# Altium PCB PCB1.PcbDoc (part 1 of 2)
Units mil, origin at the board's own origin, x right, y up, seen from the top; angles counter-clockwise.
Board outline 3035 x 2265 mil, 2 copper layers (Top Layer, Bottom Layer); 66 components, 70 nets, 274 pads, 24 vias.
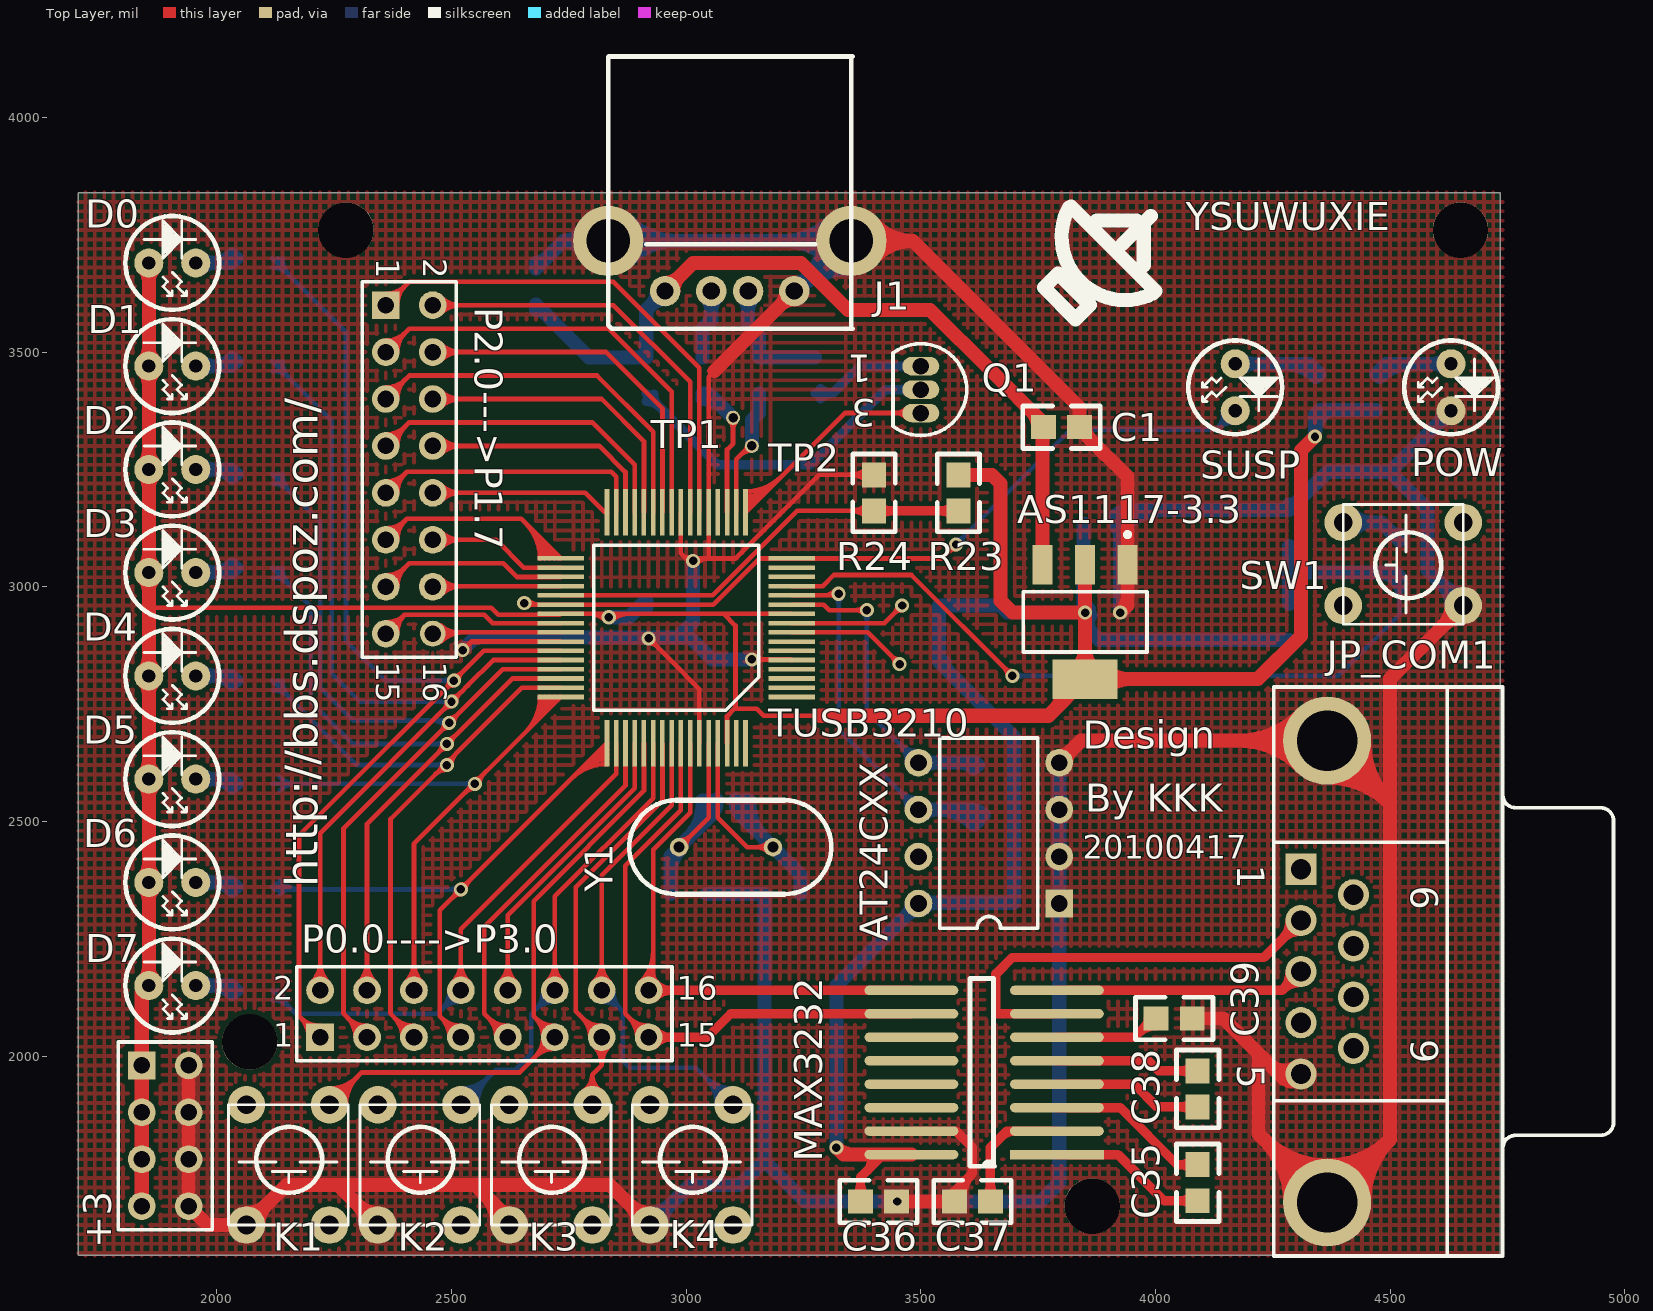
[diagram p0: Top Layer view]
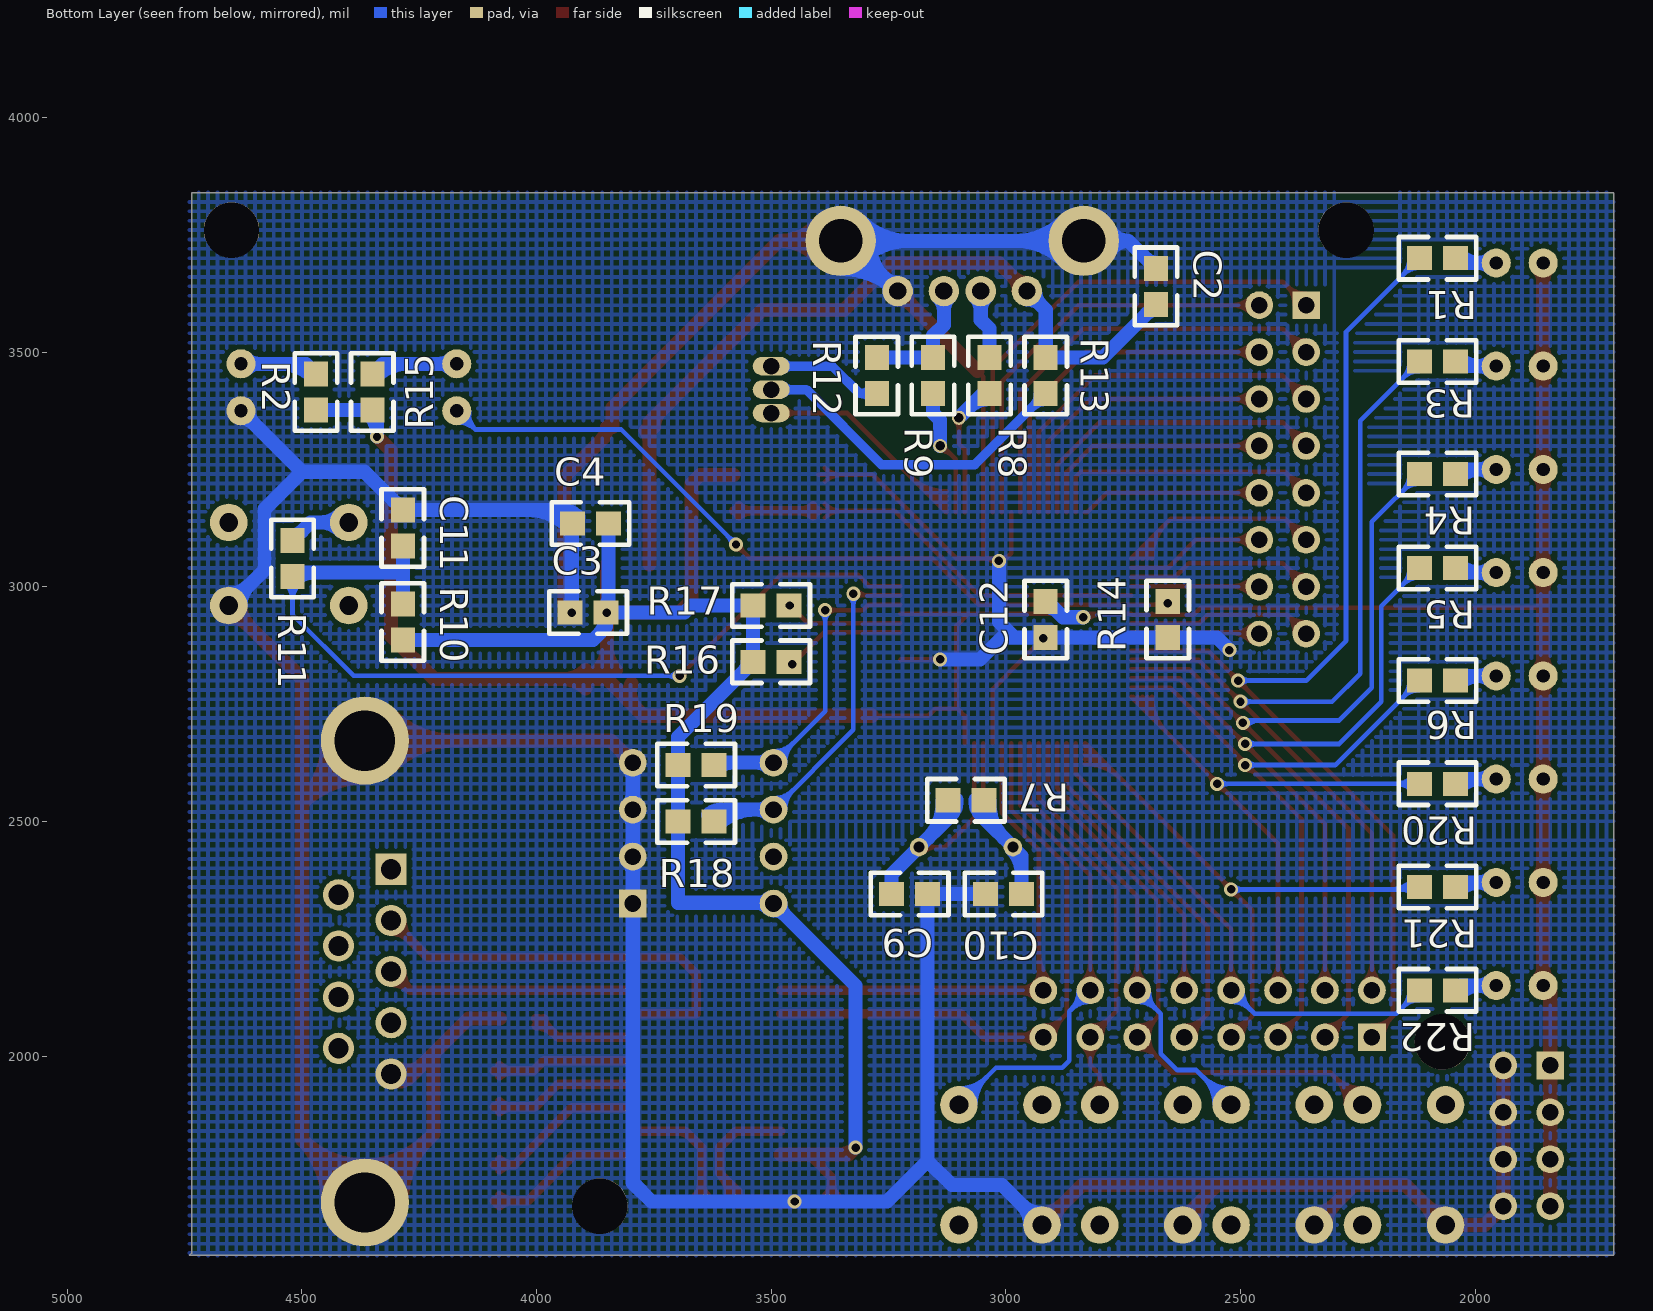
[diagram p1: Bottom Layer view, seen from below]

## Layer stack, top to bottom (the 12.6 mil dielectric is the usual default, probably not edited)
Top Layer: signal copper 1.4
Dielectric: dielectric 12.6, FR-4, Dk 4.8
Bottom Layer: signal copper 1.4

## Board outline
1705,3840 1705,1575 4740,1575 4735,1580 4735,3840

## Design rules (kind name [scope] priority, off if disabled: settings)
Clearance [All] p1: gap=5
HoleSize [All] p1: absolutevalues=TRUE maxlimit=300 minlimit=1 maxpercent=80.000 minpercent=20.000
PolygonConnect [All] p1: connectstyle=Direct reliefconductorwidth=10 reliefentries=4 polygonreliefangle="90 Angle"
RoutingVias [All] p1: holewidth=18 width=30 viastyle="Through Hole" minholewidth=18 minwidth=30 maxholewidth=18 maxwidth=30
SilkscreenOverComponentPads [All] p1: minsilkscreentomaskgap=10
SolderMaskExpansion [All] p1: expansion=4
TestPointUsage [All] p1: valid=0 allowmultiple=FALSE
Testpoint [All] p1: side=15 testpointundercomponent=TRUE minsize=40 maxsize=100 preferedsize=60 minholesize=0 maxholesize=40 preferedholesize=32 testpointgrid=1 style=1023 order=0123456789
Width [All] p1: maxlimit=50 minlimit=5 preferedwidth=50
22 further rules are at their usual default settings.

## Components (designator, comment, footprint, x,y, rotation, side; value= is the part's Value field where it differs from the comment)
+3 "Header 4X2" HDR2X4 1840,1980 r270 top (schematic designator "+3.3  GND")
AS1117-3.3 "AS1117-3.3" DSO-G3 3850,2925 r180 top
AT24CXX "24LCxx" DIP-8 3645,2475 r90 top (schematic designator U5)
C1 "Cap" C0805 3800,3340 r180 top
C2 "Cap" C0805 2680,3640 r270 bottom
C3 "Cap" C0805 3890,2945 r180 bottom
C4 "Cap" C0805 3885,3135 r180 bottom
C9 "Cap" C0805 3205,2345 r180 bottom
C10 "Cap" C0805 3005,2345 r0 bottom
C11 "Cap" C0805 4285,3125 r90 bottom
C12 "Cap" C0805 2915,2930 r90 bottom
C35 "Cap" C0805 4090,1730 r90 top
C36 "Cap" C0805 3410,1690 r0 top
C37 "Cap" C0805 3610,1690 r0 top
C38 "Cap" C0805 4090,1930 r90 top
C39 "Cap" C0805 4040,2080 r180 top
D0 "LED1" LED 1855,3690 r0 top
D1 "LED1" LED 1855,3470 r0 top
D2 "LED1" LED 1855,3250 r0 top
D3 "LED1" LED 1855,3030 r0 top
D4 "LED1" LED 1855,2810 r0 top
D5 "LED1" LED 1855,2590 r0 top
D6 "LED1" LED 1855,2370 r0 top
D7 "LED1" LED 1855,2150 r0 top
J1 "USB_A" USB-A 2955,3630 r180 top
JP_COM1 "D Connector 9" DSUB1.385-2H9 4740,2180 r270 top
K1 "Button" SW-6 2240,1640 r90 top
K2 "Button" SW-6 2520,1640 r90 top
K3 "Button" SW-6 2800,1640 r90 top
K4 "Button" SW-6 3100,1640 r90 top
MAX3232 "MAX3232" SOP16 3770,1790 r180 top (schematic designator U6)
P0.0---->P3.0 "Header 8X2" HDR2X8#1 2220,2040 r0 top (schematic designator P1)
P2.0--->P1.7 "Header 8X2" HDR2X8#2 2360,3600 r270 top (schematic designator P2)
POW "LED1" LED 4630,3475 r270 top
Q1 "2N3904" TO-92A 3500,3420 r180 top
R1 "Res2" c0805 2080,3700 r180 bottom
R2 "Res2" c0805 4470,3415 r90 bottom
R3 "Res2" c0805 2080,3480 r180 bottom
R4 "Res2" c0805 2080,3240 r180 bottom
R5 "Res2" c0805 2080,3040 r180 bottom
R6 "Res2" c0805 2080,2800 r180 bottom
R7 "Res2" c0805 3085,2545 r180 bottom
R8 "Res2" c0805 3035,3450 r270 bottom
R9 "Res2" c0805 3155,3450 r270 bottom
R10 "Res2" c0805 4285,2925 r270 bottom
R11 "Res2" c0805 4520,3060 r270 bottom
R12 "Res2" c0805 3275,3450 r90 bottom
R13 "Res2" c0805 2915,3450 r90 bottom
R14 "Res2" c0805 2655,2930 r270 bottom
R15 "Res2" c0805 4350,3415 r90 bottom
R16 "Res2" c0805 3500,2840 r180 bottom
R17 "Res2" c0805 3500,2960 r180 bottom
R18 "Res2" c0805 3660,2500 r0 bottom
R19 "Res2" c0805 3660,2620 r0 bottom
R20 "Res2" c0805 2080,2580 r180 bottom
R21 "Res2" c0805 2080,2360 r180 bottom
R22 "Res2" c0805 2080,2140 r180 bottom
R23 "Res2" c0805 3580,3200 r90 top
R24 "Res2" c0805 3400,3200 r270 top
SUSP "LED1" LED 4170,3475 r270 top
SW1 "Button" SW-6 4400,2960 r0 top
TP1 "TestPoint" TESTPOINT 3100,3360 r90 top
TP2 "TestPoint" TESTPOINT 3140,3300 r90 top
TUSB3210 "TUSB3210" Quad64 3225,2765 r180 top (schematic designator U3)
Y1 "XTAL" GJA-M 3085,2445 r180 top
? "Comment" WXDAHZ 3880,3680 r0 top

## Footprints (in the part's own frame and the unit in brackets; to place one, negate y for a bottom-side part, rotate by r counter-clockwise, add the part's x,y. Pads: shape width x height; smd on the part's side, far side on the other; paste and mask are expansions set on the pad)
C0805 [mm]
  rect 1.35x1.3 smd: 1(-0.975,0) 2(0.975,0)
  silkscreen extent -2.1,-1.15 2.1,1.15
c0805 [mm]
  rect 1.35x1.3 smd: 1(-0.975,0) 2(0.975,0)
  silkscreen extent -2.1,-1.15 2.1,1.15
DIP-8 [mm] "DIP; 8 Leads; Row Spacing 7.62 mm; Pitch 2.54 mm"
  rect 1.5x1.5 hole 0.9: 1(-3.81,-3.81)
  round 1.5 hole 0.9: 2(-1.27,-3.81) 3(1.27,-3.81) 4(3.81,-3.81) 5(3.81,3.81) 6(1.27,3.81) 7(-1.27,3.81) 8(-3.81,3.81)
  silkscreen extent -5.15,-2.65 5.15,2.65
DSO-G3 [mm]
  rect 1.1x2.15 smd: 1(-2.3,-3.1) 2(0,-3.1) 3(2.3,-3.1)
  rect 3.5x2.15 smd: 4(0,3.1)
  silkscreen extent -3.35,-4.85 3.35,1.63
DSUB1.385-2H9 [mm] "Connector; D Subminiature; 9 Position; Right Angle; Pitch 1.385 mm"
  rect 1.69x1.69 hole 1.09: 1(-5.54,-10.92)
  round 1.69 hole 1.09: 2(-2.77,-10.92) 3(0,-10.92) 4(2.77,-10.92) 5(5.54,-10.92) 6(-4.155,-8.08) 7(-1.385,-8.08) 8(1.385,-8.08) 9(4.155,-8.08)
  round 4.76 hole 3.26: 10(-12.495,-9.5) 11(12.495,-9.5)
  silkscreen extent -15.4,-12.4 15.4,6
GJA-M [mm]
  round 1 hole 0.6: 1(-2.54,0) 2(2.54,0)
  silkscreen extent -5.69,-2.54 5.23,2.54
HDR2X4 [mm] "Connector; Header; 4x2 Position"
  rect 1.5x1.5 hole 0.9: 1(0,0)
  round 1.5 hole 0.9: 2(0,2.54) 3(2.54,0) 4(2.54,2.54) 5(5.08,0) 6(5.08,2.54) 7(7.62,0) 8(7.62,2.54)
  silkscreen extent -1.27,-1.27 8.89,3.81
HDR2X8#1 [mm] "Connector; Header; 8x2 Position"
  rect 1.5x1.5 hole 0.9: 1(0,0)
  round 1.5 hole 0.9: 2(0,2.54) 3(2.54,0) 4(2.54,2.54) 5(5.08,0) 6(5.08,2.54) 7(7.62,0) 8(7.62,2.54) 9(10.16,0) 10(10.16,2.54) 11(12.7,0) 12(12.7,2.54) 13(15.24,0) 14(15.24,2.54) 15(17.78,0) 16(17.78,2.54)
  silkscreen extent -1.27,-1.27 19.05,3.81
HDR2X8#2 [mm] "Connector; Header; 8x2 Position"
  rect 1.5x1.5 hole 0.9: 1(0,0)
  round 1.5 hole 0.9: 2(0,2.54) 3(2.54,0) 4(2.54,2.54) 5(5.08,0) 6(5.08,2.54) 7(7.62,0) 8(7.62,2.54) 9(10.16,0) 10(10.16,2.54) 11(12.7,0) 12(12.7,2.54) 13(15.24,0) 14(15.24,2.54) 15(17.78,0)
  round 1.397 hole 0.9: 16(17.78,2.54)
  silkscreen extent -1.27,-1.27 19.05,3.81
LED [mil]
  round 62 hole 28: 1(0,0) 2(100,0)
  silkscreen extent -50,-100 150,100
Quad64 [mm]
  rect 2.5x0.25 smd: 1(0,0) 2(0,-0.5) 3(0,-1) 4(0,-1.5) 5(0,-2) 6(0,-2.5) 7(0,-3) 8(0,-3.5) 9(0,-4) 10(0,-4.5) 11(0,-5) 12(0,-5.5) 13(0,-6) 14(0,-6.5) 15(0,-7) 16(0,-7.5) 33(12.5,-7.5) 34(12.5,-7) 35(12.5,-6.5) 36(12.5,-6) 37(12.5,-5.5) 38(12.5,-5) 39(12.5,-4.5) 40(12.5,-4) 41(12.5,-3.5) 42(12.5,-3) 43(12.5,-2.5) 44(12.5,-2) 45(12.5,-1.5) 46(12.5,-1) 47(12.5,-0.5) 48(12.5,0)
  rect 0.25x2.5 smd: 17(2.5,-10) 18(3,-10) 19(3.5,-10) 20(4,-10) 21(4.5,-10) 22(5,-10) 23(5.5,-10) 24(6,-10) 25(6.5,-10) 26(7,-10) 27(7.5,-10) 28(8,-10) 29(8.5,-10) 30(9,-10) 31(9.5,-10) 32(10,-10) 49(10,2.5) 50(9.5,2.5) 51(9,2.5) 52(8.5,2.5) 53(8,2.5) 54(7.5,2.5) 55(7,2.5) 56(6.5,2.5) 57(6,2.5) 58(5.5,2.5) 59(5,2.5) 60(4.5,2.5) 61(4,2.5) 62(3.5,2.5) 63(3,2.5) 64(2.5,2.5)
  silkscreen extent 1.79,-8.21 10.71,0.71
SOP16 [mil]
  rect 200x20 smd: 1(-20,0)
  oval 200x20 smd: 2(-20,-50) 3(-20,-100) 4(-20,-150) 5(-20,-200) 6(-20,-250) 7(-20,-300) 8(-20,-350) 9(290,-350) 10(290,-300) 11(290,-250) 12(290,-200) 13(290,-150) 14(290,-100) 15(290,-50) 16(290,0)
  silkscreen extent 112,-375 165,25
SW-6 [mil]
  round 80 hole 40: 1(0,0) 2(0,177) 3(256,0) 4(256,177)
  silkscreen extent 0,-40 256,215
TESTPOINT [mil]
  round 30 hole 20: 1(0,0)
TO-92A [mm] "TO, Flat Index; 3 In-Line, Axial Leads; Body Dia. 4.5mm; Leads 0.51 x 0.48 mm (max)"
  oval 2x1 hole 0.9: 1(0,-1.27) 2(0,0) 3(0,1.27)
  silkscreen extent -2.48,-2.48 1.5,2.48
USB-A [mil]
  round 65 hole 37: 1(0,0) 2(-98.5,0) 3(-177,0) 4(-275.6,0)
  round 150 hole 93: 5(121,-107) 6(-397,-107)
  silkscreen extent -400,-500 121,80
WXDAHZ [mil]
  silkscreen extent -118,-110 120,130

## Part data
+3: "Header, 4-Pin, Dual row"
C1 C2 C3 C4 C9 C10 C11 C12 C35 C36 C37 C38 C39: "Capacitor"
D0 D1 D2 D3 D4 D5 D6 D7 POW SUSP: "Typical RED GaAs LED"
JP_COM1: "Receptacle Assembly, 9 Position, Right Angle"
K1 K2 K3 K4 SW1: library part Button_4
P0.0---->P3.0 P2.0--->P1.7: "Header, 8-Pin, Dual row"
Q1: "NPN General Purpose Amplifier"
R1 R2 R3 R4 R5 R6 R7 R8 R9 R10 R11 R12 R13 R14 R15 R16 R17 R18 R19 R20 R21 R22 R23 R24: "Resistor"
TP1 TP2: "TespPoint"
Y1: "Crystal Oscillator"

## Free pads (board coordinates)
  round 118.11 hole 118.11: 0(2070,2030) 0(3865,1680) 1(4650,3760) 2(2275,3760)

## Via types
v1: diameter 30, hole 18, Top Layer to Bottom Layer, 24 vias

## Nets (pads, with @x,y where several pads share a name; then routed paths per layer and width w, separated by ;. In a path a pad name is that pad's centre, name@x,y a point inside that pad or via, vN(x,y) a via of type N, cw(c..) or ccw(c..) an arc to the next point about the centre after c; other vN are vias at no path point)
+1.8: R23.1 R24.2 TUSB3210.37 | length 1118
  Top Layer w10: TUSB3210.37@2732.87,2981.53 3056.53,2981.53 3236.61,3161.61 R24.2@3400,3161.61 ; R24.2@3385.44,3147.05 ccw(c3350.29,3111.9) 3350.29,3161.61 ccw(c3350.29,3211.32) R24.2@3385.44,3176.17
  Top Layer w20: R24.2@3400,3161.61 R23.1@3580,3161.61 ; R24.2@3411.02,3150.59 cw(c3437.64,3123.98) 3437.64,3161.61 cw(c3437.64,3199.25) R24.2@3411.02,3172.64 ; R23.1@3568.98,3150.59 ccw(c3542.36,3123.98) 3542.36,3161.61 ccw(c3542.36,3199.25) R23.1@3568.98,3172.64
+3.3: +3.1 +3.3 +3.5 +3.7 AS1117-3.3.2 AS1117-3.3.4 AT24CXX.8 C3.2 C4.2 C12.2 C36.1 D0.1 D1.1 D2.1 D3.1 D4.1 D5.1 D6.1 D7.1 MAX3232.16 R2.1 R10.2 R15.1 R16.1 R17.1 R18.2 R19.2 R23.2 TUSB3210.10 TUSB3210.39 TUSB3210.62 | length 12761.5
  Top Layer w10: 1855,2955 2585,2955 2600,2940 2730.71,2940 TUSB3210.39@2732.87,2942.16 3080,2942.16 ; 2683.55,2940 ccw(c2683.55,2947.2) TUSB3210.39@2688.64,2942.11 ; 2793.56,2942.16 cw(c2793.56,2893.56) v1@2827.93,2927.93 ; 2817.7,2942.16 cw(c2817.7,2917.7) v1(2835,2935) cw(c2852.3,2917.7) 2852.3,2942.16 ; v1@2842.07,2927.93 cw(c2876.44,2893.56) 2876.44,2942.16 ; TUSB3210.62@3087.2,2666.57 3087.2,2724.41 3102.8,2740 3105,2740 ; TUSB3210.10@3225,2942.16 3080,2942.16 ; 3285,2725 3165,2725 3150,2740 3105,2740 ; 3080,2942.16 3105,2917.16 3105,2740
  Top Layer w20: C36.1@3371.61,1690 3371.61,1741.61 3420,1790 MAX3232.16@3480,1790 ; 3371.61,1727.64 cw(c3333.98,1727.64) 3360.59,1701.02 ccw(c3333.98,1727.64) 3371.61,1727.64 ; 3371.61,1727.64 ccw(c3409.25,1727.64) 3382.64,1701.02 cw(c3409.25,1727.64) 3371.61,1727.64 ; 3386.61,1756.61 ccw(c3367.85,1775.38) 3390,1790 cw(c3367.85,1775.38) 3386.61,1756.61
  Top Layer w30: +3.7@1840,1680 +3.5@1840,1780 +3.3@1840,1880 +3.1@1840,1980 1840,2135 D7.1@1855,2150 D6.1@1855,2370 D5.1@1855,2590 D4.1@1855,2810 1855,2955 D3.1@1855,3030 D2.1@1855,3250 D1.1@1855,3470 D0.1@1855,3690 ; 3285,2725 3772.05,2725 AS1117-3.3.4@3850,2802.95 ; 3356.21,1790 cw(c3356.21,1841.21) v1(3320,1805) 3335,1790 MAX3232.16@3480,1790 ; R23.2@3580,3238.39 3651.61,3238.39 3670,3220 3670,2970 3695,2945 v1(3850,2945) ; 3785.34,2738.29 ccw(c3747.88,2775.75) AS1117-3.3.4@3797.72,2793.7 ; AS1117-3.3.4@3830.68,2822.27 ccw(c3784.04,2868.92) 3850,2868.92 ccw(c3915.96,2868.92) AS1117-3.3.4@3869.32,2822.27 ; AS1117-3.3.2@3850,3047.05 v1(3850,2945) ; AS1117-3.3.4@3895.89,2783.63 cw(c3942.54,2736.99) 3942.54,2802.95 cw(c3942.54,2868.92) AS1117-3.3.4@3895.89,2822.27 ; v1(4340,3320) 4310,3290 4310,2895 4217.95,2802.95 AS1117-3.3.4@3850,2802.95 ; D7.1@1843.69,2161.31 ccw(c1816.37,2188.63) 1855,2188.63 ; D7.1@1843.69,2161.31 ccw(c1816.37,2188.63) 1855,2188.63 ; D7.1@1843.69,2161.31 ccw(c1816.37,2188.63) 1855,2188.63 ; D6.1@1843.69,2358.69 cw(c1816.37,2331.37) 1855,2331.37 ; D6.1@1843.69,2358.69 cw(c1816.37,2331.37) 1855,2331.37 ; D6.1@1843.69,2358.69 cw(c1816.37,2331.37) 1855,2331.37 ; D6.1@1843.69,2381.31 ccw(c1816.37,2408.63) 1855,2408.63 ; D6.1@1843.69,2381.31 ccw(c1816.37,2408.63) 1855,2408.63 ; D6.1@1843.69,2381.31 ccw(c1816.37,2408.63) 1855,2408.63 ; D5.1@1843.69,2578.69 cw(c1816.37,2551.37) 1855,2551.37 ; D5.1@1843.69,2578.69 cw(c1816.37,2551.37) 1855,2551.37 ; D5.1@1843.69,2578.69 cw(c1816.37,2551.37) 1855,2551.37 ; D5.1@1843.69,2601.31 ccw(c1816.37,2628.63) 1855,2628.63 ; D5.1@1843.69,2601.31 ccw(c1816.37,2628.63) 1855,2628.63 ; D5.1@1843.69,2601.31 ccw(c1816.37,2628.63) 1855,2628.63 ; D4.1@1843.69,2798.69 cw(c1816.37,2771.37) 1855,2771.37 ; D4.1@1843.69,2798.69 cw(c1816.37,2771.37) 1855,2771.37 ; D4.1@1843.69,2798.69 cw(c1816.37,2771.37) 1855,2771.37 ; D4.1@1843.69,2821.31 ccw(c1816.37,2848.63) 1855,2848.63 ; D4.1@1843.69,2821.31 ccw(c1816.37,2848.63) 1855,2848.63 ; D4.1@1843.69,2821.31 ccw(c1816.37,2848.63) 1855,2848.63 ; D3.1@1843.69,3018.69 cw(c1816.37,2991.37) 1855,2991.37 ; D3.1@1843.69,3018.69 cw(c1816.37,2991.37) 1855,2991.37 ; D3.1@1843.69,3018.69 cw(c1816.37,2991.37) 1855,2991.37 ; D3.1@1843.69,3041.31 ccw(c1816.37,3068.63) 1855,3068.63 ; D3.1@1843.69,3041.31 ccw(c1816.37,3068.63) 1855,3068.63 ; D3.1@1843.69,3041.31 ccw(c1816.37,3068.63) 1855,3068.63 ; D2.1@1843.69,3238.69 cw(c1816.37,3211.37) 1855,3211.37 ; D2.1@1843.69,3238.69 cw(c1816.37,3211.37) 1855,3211.37 ; D2.1@1843.69,3238.69 cw(c1816.37,3211.37) 1855,3211.37 ; D2.1@1843.69,3261.31 ccw(c1816.37,3288.63) 1855,3288.63 ; D2.1@1843.69,3261.31 ccw(c1816.37,3288.63) 1855,3288.63 ; D2.1@1843.69,3261.31 ccw(c1816.37,3288.63) 1855,3288.63 ; D1.1@1843.69,3458.69 cw(c1816.37,3431.37) 1855,3431.37 ; D1.1@1843.69,3458.69 cw(c1816.37,3431.37) 1855,3431.37 ; D1.1@1843.69,3458.69 cw(c1816.37,3431.37) 1855,3431.37 ; D1.1@1843.69,3481.31 ccw(c1816.37,3508.63) 1855,3508.63 ; D1.1@1843.69,3481.31 ccw(c1816.37,3508.63) 1855,3508.63 ; D1.1@1843.69,3481.31 ccw(c1816.37,3508.63) 1855,3508.63 ; D0.1@1843.69,3678.69 cw(c1816.37,3651.37) 1855,3651.37 ; D0.1@1843.69,3678.69 cw(c1816.37,3651.37) 1855,3651.37 ; D0.1@1843.69,3678.69 cw(c1816.37,3651.37) 1855,3651.37 ; 1855,2188.63 ccw(c1893.63,2188.63) D7.1@1866.31,2161.31 ; 1855,2188.63 ccw(c1893.63,2188.63) D7.1@1866.31,2161.31 ; 1855,2188.63 ccw(c1893.63,2188.63) D7.1@1866.31,2161.31 ; 1855,2331.37 cw(c1893.63,2331.37) D6.1@1866.31,2358.69 ; 1855,2331.37 cw(c1893.63,2331.37) D6.1@1866.31,2358.69 ; 1855,2331.37 cw(c1893.63,2331.37) D6.1@1866.31,2358.69 ; 1855,2408.63 ccw(c1893.63,2408.63) D6.1@1866.31,2381.31 ; 1855,2408.63 ccw(c1893.63,2408.63) D6.1@1866.31,2381.31 ; 1855,2408.63 ccw(c1893.63,2408.63) D6.1@1866.31,2381.31 ; 1855,2551.37 cw(c1893.63,2551.37) D5.1@1866.31,2578.69 ; 1855,2551.37 cw(c1893.63,2551.37) D5.1@1866.31,2578.69 ; 1855,2551.37 cw(c1893.63,2551.37) D5.1@1866.31,2578.69 ; 1855,2628.63 ccw(c1893.63,2628.63) D5.1@1866.31,2601.31 ; 1855,2628.63 ccw(c1893.63,2628.63) D5.1@1866.31,2601.31 ; 1855,2628.63 ccw(c1893.63,2628.63) D5.1@1866.31,2601.31 ; 1855,2771.37 cw(c1893.63,2771.37) D4.1@1866.31,2798.69 ; 1855,2771.37 cw(c1893.63,2771.37) D4.1@1866.31,2798.69 ; 1855,2771.37 cw(c1893.63,2771.37) D4.1@1866.31,2798.69 ; 1855,2848.63 ccw(c1893.63,2848.63) D4.1@1866.31,2821.31 ; 1855,2848.63 ccw(c1893.63,2848.63) D4.1@1866.31,2821.31 ; 1855,2848.63 ccw(c1893.63,2848.63) D4.1@1866.31,2821.31 ; 1855,2991.37 cw(c1893.63,2991.37) D3.1@1866.31,3018.69 ; 1855,2991.37 cw(c1893.63,2991.37) D3.1@1866.31,3018.69 ; 1855,2991.37 cw(c1893.63,2991.37) D3.1@1866.31,3018.69 ; 1855,3068.63 ccw(c1893.63,3068.63) D3.1@1866.31,3041.31 ; 1855,3068.63 ccw(c1893.63,3068.63) D3.1@1866.31,3041.31 ; 1855,3068.63 ccw(c1893.63,3068.63) D3.1@1866.31,3041.31 ; 1855,3211.37 cw(c1893.63,3211.37) D2.1@1866.31,3238.69 ; 1855,3211.37 cw(c1893.63,3211.37) D2.1@1866.31,3238.69 ; 1855,3211.37 cw(c1893.63,3211.37) D2.1@1866.31,3238.69 ; 1855,3288.63 ccw(c1893.63,3288.63) D2.1@1866.31,3261.31 ; 1855,3288.63 ccw(c1893.63,3288.63) D2.1@1866.31,3261.31 ; 1855,3288.63 ccw(c1893.63,3288.63) D2.1@1866.31,3261.31 ; 1855,3431.37 cw(c1893.63,3431.37) D1.1@1866.31,3458.69 ; 1855,3431.37 cw(c1893.63,3431.37) D1.1@1866.31,3458.69 ; 1855,3431.37 cw(c1893.63,3431.37) D1.1@1866.31,3458.69 ; 1855,3508.63 ccw(c1893.63,3508.63) D1.1@1866.31,3481.31 ; 1855,3508.63 ccw(c1893.63,3508.63) D1.1@1866.31,3481.31 ; 1855,3508.63 ccw(c1893.63,3508.63) D1.1@1866.31,3481.31 ; 1855,3651.37 cw(c1893.63,3651.37) D0.1@1866.31,3678.69 ; 1855,3651.37 cw(c1893.63,3651.37) D0.1@1866.31,3678.69 ; 1855,3651.37 cw(c1893.63,3651.37) D0.1@1866.31,3678.69 ; AS1117-3.3.4@3850,2802.95 v1(3850,2945)
  Bottom Layer w30: v1(2835,2935) 2877.94,2935 2911.32,2968.39 C12.2@2915,2968.39 ; 2888.96,2946.03 cw(c2915,2919.99) C12.2@2915,2956.81 ; v1(3320,1805) 3320,2150 AT24CXX.8@3495,2325 3496.61,2326.61 3698.39,2326.61 R18.2@3698.39,2500 R19.2@3698.39,2620 3698.39,2680 R16.1@3538.39,2840 R17.1@3538.39,2960 3670,2960 3685,2945 v1(3850,2945) C3.2@3851.61,2945 ; AT24CXX.8@3480.47,2325 cw(c3445.4,2325) 3470.2,2300.2 cw(c3495,2275.4) AT24CXX.8@3495,2310.47 ; AT24CXX.8@3505.27,2314.73 cw(c3533.97,2286.03) 3533.97,2326.61 ; AT24CXX.8@3505.27,2335.27 ccw(c3526.18,2356.18) 3526.18,2326.61 ; R16.1@3549.96,2840 ccw(c3577.91,2840) R16.1@3558.15,2820.24 ; 3846.61,2980.26 ccw(c3885.89,2980.26) C3.2@3858.12,2952.49 ; C4.2@3846.61,3135 3846.61,2950 C3.2@3851.61,2945 ; 3851.61,2917.06 cw(c3880.54,2917.06) C3.2@3860.09,2937.51 ; C3.2@3861.28,2938.93 ccw(c3884.84,2922.44) 3864.51,2902.11 ; R10.2@4285,2886.61 3880,2886.61 3851.61,2915 C3.2@3851.61,2945 ; v1(4340,3320) 4340,3366.61 R15.1@4350,3376.61 R2.1@4470,3376.61 ; v1@4340,3325.92 cw(c4399.71,3325.92) R15.1@4357.49,3368.14
GND: +3.2 +3.4 +3.6 +3.8 AS1117-3.3.1 AT24CXX.1 AT24CXX.2 AT24CXX.3 AT24CXX.4 C1.1 C2.1 C3.1 C4.1 C9.2 C10.2 C11.2 C12.1 C36.2 C37.1 C39.1 J1.4 J1.5 J1.6 JP_COM1.5 JP_COM1.10 JP_COM1.11 K1.2 K2.2 K3.2 K4.2 MAX3232.15 pad.0@3865,1680 pad.1 pad.2 POW.2 R14.2 R24.1 SW1.3 TUSB3210.5 TUSB3210.21 TUSB3210.24 TUSB3210.42 TUSB3210.59 | length 22373
  Top Layer w10: v1(2523.78,2865) 2541.89,2883.11 TUSB3210.42@2732.87,2883.11 ; v1@2920,2880 cw(c2920,2855.86) 2937.07,2872.93 cw(c2954.14,2890) v1@2930,2890 ; v1(2920,2890) 2965,2845 3028.15,2781.85 TUSB3210.59@3028.15,2666.57 ; TUSB3210.24@2988.78,3158.7 2988.78,3071.22 3000,3060 3045,3060 ; 2993.78,3066.22 ccw(c3003.64,3076.08) v1@3010.26,3063.8 ; v1@3023,3049 cw(c3045,3032.5) 3045,3060 ; 3060,3459.4 3047.83,3447.24 TUSB3210.21@3047.83,3158.7 3047.83,3062.83 3045,3060 ; v1(3140,2845) 3223.74,2845 TUSB3210.5@3225,2843.74 ; v1@3147.07,2837.93 cw(c3164.14,2820.86) 3164.14,2845 cw(c3164.14,2869.14) v1@3147.07,2852.07 ; R24.1@3385.44,3223.83 ccw(c3350.29,3188.68) 3350.29,3238.39 ccw(c3350.29,3288.1) R24.1@3385.44,3252.95 ; R24.1@3400,3238.39 3283.39,3238.39 3105,3060 3045,3060
  Top Layer w20: MAX3232.15@3480,1840 3575,1840 3610,1805 3610,1750 ; C37.1@3571.61,1690 3571.61,1711.61 3610,1750 ; 3610,1750 ccw(c3663.25,1696.74) 3588.15,1691.16 cw(c3663.25,1696.74) 3610,1750 ; C37.1@3568.2,1689.67 cw(c3605.82,1692.47) 3579.15,1719.15 ccw(c3605.82,1692.47) C37.1@3568.2,1689.67
  Top Layer w30: +3.2@1940,1980 +3.4@1940,1880 +3.6@1940,1780 +3.8@1940,1680 1980,1640 K1.2@2063,1640 2148,1725 2258,1725 ; K2.2@2343,1640 2258,1725 ; K3.2@2623,1640 2623,1652 2550,1725 ; K4.2@2923,1640 2838,1725 2550,1725 ; 3060,3459.4 J1.4@3230.6,3630 ; J1.6@3352,3737 3483,3737 ; J1.6@3397.43,3697.81 cw(c3482.99,3624) 3482.99,3737 ; J1.6@3397.43,3776.19 ccw(c3482.99,3850) 3482.99,3737 ; C36.2@3448.39,1690 C37.1@3571.61,1690 ; AT24CXX.4@3795,2625 3841.93,2671.93 JP_COM1.10@4365.98,2671.93 4500,2537.91 ; AT24CXX.4@3795,2639.53 ccw(c3795,2674.6) 3819.8,2649.8 ccw(c3844.6,2625) AT24CXX.4@3809.53,2625 ; C1.1@3838.39,3340 3838.39,3381.61 3483,3737 ; C1.1@3849.96,3340 ccw(c3886.08,3340) C1.1@3860.54,3314.46 ; C1.1@3856.69,3318.31 3940.55,3234.45 AS1117-3.3.1@3940.55,3047.05 3940.55,2960.55 v1(3925,2945) ccw(c3887.46,2982.54) 3940.55,2982.54 ; C39.1@4078.39,2080 4145,2080 4220,2005 ; JP_COM1.5@4310.08,1961.89 4263.11,1961.89 4220,2005 ; JP_COM1.10@4310.33,2616.28 ccw(c4175.98,2481.93) 4175.98,2671.93 ccw(c4175.98,2861.93) JP_COM1.10@4310.33,2727.58 ; JP_COM1.10@4331.55,2637.49 ccw(c4248.41,2554.36) 4248.41,2671.93 ccw(c4248.41,2789.5) JP_COM1.10@4331.55,2706.37 ; SW1.3@4631,2960 cw(c4570.64,2960) 4613.32,2917.32 cw(c4656,2874.64) SW1.3@4656,2935 ; SW1.3@4656,2960 4500,2804 4500,2537.91 ; 2105.68,1682.68 cw(c2063,1725.36) 2063,1665 ccw(c2063,1725.36) 2105.68,1682.68 ; 2105.68,1682.68 ccw(c2148.36,1640) 2088,1640 cw(c2148.36,1640) 2105.68,1682.68 ; 2258,1725 2550,1725 ; 2300.32,1682.68 cw(c2257.64,1640) 2318,1640 ccw(c2257.64,1640) 2300.32,1682.68 ; 2300.32,1682.68 ccw(c2343,1725.36) 2343,1665 cw(c2343,1725.36) 2300.32,1682.68 ; 2880.32,1682.68 cw(c2837.64,1640) 2898,1640 ccw(c2837.64,1640) 2880.32,1682.68 ; 2880.32,1682.68 ccw(c2923,1725.36) 2923,1665 cw(c2923,1725.36) 2880.32,1682.68 ; 3200.72,3600.13 cw(c3230.6,3570.25) J1.4@3230.6,3612.5 ; 3200.72,3600.13 ccw(c3170.85,3630) J1.4@3213.1,3630 ; 3200.72,3600.13 cw(c3230.6,3570.25) J1.4@3230.6,3612.5 ; 3200.72,3600.13 ccw(c3170.85,3630) J1.4@3213.1,3630 ; 3200.72,3600.13 ccw(c3170.85,3630) J1.4@3213.1,3630 ; 3200.72,3600.13 cw(c3230.6,3570.25) J1.4@3230.6,3612.5 ; 4220,2005 4220,1834.06 JP_COM1.11@4365.98,1688.07 4500,1822.09 ; 4231.63,1822.42 cw(c4097.28,1688.07) 4287.28,1688.07 ccw(c4097.28,1688.07) 4231.63,1822.42 ; 4231.63,1822.42 ccw(c4365.98,1956.77) 4365.98,1766.77 cw(c4365.98,1956.77) 4231.63,1822.42 ; 4265.98,1961.89 cw(c4265.98,1917.79) 4297.16,1948.97 ccw(c4265.98,1917.79) 4265.98,1961.89 ; 4265.98,1961.89 ccw(c4265.98,2005.99) 4297.16,1974.81 cw(c4265.98,2005.99) 4265.98,1961.89 ; 4282.85,1771.21 cw(c4199.71,1688.07) 4317.28,1688.07 ccw(c4199.71,1688.07) 4282.85,1771.21 ; 4282.85,1771.21 ccw(c4365.98,1854.35) 4365.98,1736.77 cw(c4365.98,1854.35) 4282.85,1771.21 ; 4448.91,1771 cw(c4366.28,1853.63) 4366.07,1736.77 ccw(c4366.28,1853.63) 4448.91,1771 ; 4448.91,1771 ccw(c4531.54,1688.37) 4414.68,1688.16 cw(c4531.54,1688.37) 4448.91,1771 ; 4448.91,2589 cw(c4531.54,2671.63) 4414.68,2671.84 ccw(c4531.54,2671.63) 4448.91,2589 ; 4448.91,2589 ccw(c4366.28,2506.37) 4366.07,2623.23 cw(c4366.28,2506.37) 4448.91,2589 ; 4499.99,1822.08 cw(c4366.47,1955.61) 4366.13,1766.77 ccw(c4366.47,1955.61) 4499.99,1822.08 ; 4499.99,1822.08 ccw(c4633.52,1688.55) 4444.69,1688.21 cw(c4633.52,1688.55) 4499.99,1822.08 ; 4500,1822.09 4500,2537.91 ; 4499.99,2537.92 cw(c4633.52,2671.45) 4444.69,2671.79 ccw(c4633.52,2671.45) 4499.99,2537.92 ; 4499.99,2537.92 ccw(c4366.47,2404.39) 4366.13,2593.23 cw(c4366.47,2404.39) 4499.99,2537.92 ; 2571.84,1703.16 cw(c2508.67,1640) 2598,1640 ccw(c2508.67,1640) 2571.84,1703.16 ; 2600.81,1674.19 ccw(c2623,1696.38) 2623,1665 cw(c2623,1696.38) 2600.81,1674.19 ; 4243.49,1981.51 ccw(c4274.3,2012.32) 4299.51,1976.79 cw(c4274.3,2012.32) 4243.49,1981.51 ; 4268.61,1956.39 ccw(c4295.15,1982.93) 4316.87,1952.32 cw(c4295.15,1982.93) 4268.61,1956.39
  Bottom Layer w30: v1(2523.78,2865) 2550.39,2891.61 R14.2@2655,2891.61 C12.1@2915,2891.61 2981.61,2891.61 ; C2.1@2680,3678.39 2738.61,3737 ; C2.1@2680,3689.96 ccw(c2680,3717.91) C2.1@2699.76,3698.15 ; J1.5@2779.92,3711.02 ccw(c2738.62,3691.19) 2738.62,3737 ; J1.5@2779.92,3762.98 cw(c2738.62,3782.81) 2738.62,3737 ; K4.2@2923,1640 3008,1725 3115,1725 3166.61,1776.61 ; v1(3015,3055) 3015,2925 2981.61,2891.61 ; C10.2@3043.39,2345 C9.2@3166.61,2345 3166.61,1776.61 ; v1(3140,2845) 3055,2845 3008.39,2891.61 2981.61,2891.61 ; J1.4@3230.6,3630 J1.6@3337.6,3737 ; J1.6@3352,3737 J1.6@3337.6,3737 ; AT24CXX.1@3784.73,2314.73 cw(c3759.93,2289.93) 3795,2289.93 cw(c3830.07,2289.93) AT24CXX.1@3805.27,2314.73 ; AT24CXX.1@3784.73,2335.27 ccw(c3759.93,2360.07) 3795,2360.07 ccw(c3830.07,2360.07) AT24CXX.1@3805.27,2335.27 ; AT24CXX.2@3784.73,2414.73 cw(c3759.93,2389.93) 3795,2389.93 cw(c3830.07,2389.93) AT24CXX.2@3805.27,2414.73 ; AT24CXX.2@3784.73,2435.27 ccw(c3759.93,2460.07) 3795,2460.07 ccw(c3830.07,2460.07) AT24CXX.2@3805.27,2435.27 ; AT24CXX.3@3784.73,2514.73 cw(c3759.93,2489.93) 3795,2489.93 cw(c3830.07,2489.93) AT24CXX.3@3805.27,2514.73 ; AT24CXX.3@3784.73,2535.27 ccw(c3759.93,2560.07) 3795,2560.07 ccw(c3830.07,2560.07) AT24CXX.3@3805.27,2535.27 ; AT24CXX.4@3784.73,2614.73 cw(c3759.93,2589.93) 3795,2589.93 cw(c3830.07,2589.93) AT24CXX.4@3805.27,2614.73 ; AT24CXX.4@3795,2625 AT24CXX.3@3795,2525 AT24CXX.2@3795,2425 AT24CXX.1@3795,2325 3795,1730 3755,1690 v1(3450,1690) 3253.23,1690 3166.61,1776.61 ; C4.1@3910.65,3148.72 cw(c3946.04,3113.33) 3946.04,3163.39 ; C4.1@3916.88,3127.51 cw(c3897.28,3107.91) 3925,3107.91 ; v1(3925,2945) C3.1@3928.39,2945 3925,2948.39 3925,3133.39 C4.1@3923.39,3135 3951.77,3163.39 C11.2@4285,3163.39 4366.61,3245 4500,3245 ; 3925,2976.37 ccw(c3958.77,2976.37) C3.1@3934.89,2952.49 ; C4.1@3931.86,3127.51 cw(c4018.47,3040.9) 4018.47,3163.39 ; C11.2@4285,3174.96 ccw(c4285,3202.91) C11.2@4304.76,3183.15 ; POW.2@4614,3375 cw(c4575.37,3375) 4602.69,3347.69 cw(c4630,3320.37) POW.2@4630,3359 ; POW.2@4630,3375 4500,3245 ; SW1.3@4631,2960 ccw(c4570.64,2960) 4613.32,3002.68 ccw(c4656,3045.36) SW1.3@4656,2985 ; SW1.3@4656,2960 4580,3036 4580,3165 4500,3245 ; 2738.61,3737 J1.5@2834,3737 J1.6@3337.6,3737 ; J1.5@2876.43,3694.57 cw(c2978.85,3592.15) 2978.85,3737 ; J1.5@2876.43,3694.57 cw(c2978.85,3592.15) 2978.85,3737 ; J1.5@2876.43,3694.57 cw(c2978.85,3592.15) 2978.85,3737 ; J1.5@2876.43,3779.43 ccw(c2978.85,3881.85) 2978.85,3737 ; J1.5@2876.43,3779.43 ccw(c2978.85,3881.85) 2978.85,3737 ; J1.5@2876.43,3779.43 ccw(c2978.85,3881.85) 2978.85,3737 ; 2965.68,1682.68 cw(c2923,1725.36) 2923,1665 ccw(c2923,1725.36) 2965.68,1682.68 ; 2965.68,1682.68 ccw(c3008.36,1640) 2948,1640 cw(c3008.36,1640) 2965.68,1682.68 ; 3207.15,3737 cw(c3207.15,3592.15) J1.6@3309.57,3694.57 ; 3207.15,3737 ccw(c3207.15,3881.85) J1.6@3309.57,3779.43 ; 3207.15,3737 cw(c3207.15,3592.15) J1.6@3309.57,3694.57 ; 3207.15,3737 ccw(c3207.15,3881.85) J1.6@3309.57,3779.43 ; 3207.15,3737 ccw(c3207.15,3881.85) J1.6@3309.57,3779.43 ; 3207.15,3737 cw(c3207.15,3592.15) J1.6@3309.57,3694.57 ; J1.4@3224.99,3624.39 cw(c3352,3497.38) J1.6@3352,3677 ; J1.4@3224.99,3624.39 cw(c3352,3497.38) J1.6@3352,3677 ; J1.4@3224.99,3624.39 cw(c3352,3497.38) J1.6@3352,3677 ; J1.4@3230.6,3647.5 ccw(c3230.6,3689.75) 3260.47,3659.87 ; J1.4@3230.6,3647.5 ccw(c3230.6,3689.75) 3260.47,3659.87 ; J1.4@3230.6,3647.5 ccw(c3230.6,3689.75) 3260.47,3659.87 ; J1.4@3248.1,3630 cw(c3290.35,3630) 3260.47,3659.87 ; J1.4@3248.1,3630 cw(c3290.35,3630) 3260.47,3659.87 ; J1.4@3248.1,3630 cw(c3290.35,3630) 3260.47,3659.87 ; 3259.76,3659.16 ccw(c3181.92,3737) J1.6@3292,3737 ; 3259.76,3659.16 ccw(c3181.92,3737) J1.6@3292,3737 ; 3259.76,3659.16 ccw(c3181.92,3737) J1.6@3292,3737 ; 3276.2,3675.6 cw(c3352,3599.8) J1.6@3352,3707 ; 3276.2,3675.6 cw(c3352,3599.8) J1.6@3352,3707 ; 3276.2,3675.6 cw(c3352,3599.8) J1.6@3352,3707
NetC9_1: C9.1 R7.1 TUSB3210.61 Y1.1 | length 1163.8
  Top Layer w10: TUSB3210.61@3067.52,2666.57 3067.52,2507.48 3130,2445 Y1.1@3185,2445 ; 3149.55,2445 cw(c3149.55,2409.55) Y1.1@3174.62,2434.62 ; 3149.55,2445 ccw(c3149.55,2480.45) Y1.1@3174.62,2455.38 ; 3149.55,2445 cw(c3149.55,2409.55) Y1.1@3174.62,2434.62 ; 3149.55,2445 ccw(c3149.55,2480.45) Y1.1@3174.62,2455.38 ; 3149.55,2445 ccw(c3149.55,2480.45) Y1.1@3174.62,2455.38 ; 3149.55,2445 cw(c3149.55,2409.55) Y1.1@3174.62,2434.62
  Bottom Layer w30: R7.1@3123.39,2545 3123.39,2506.61 Y1.1@3185,2445 3243.39,2386.61 C9.1@3243.39,2345 ; R7.1@3104.99,2546.11 ccw(c3149.52,2543.56) 3117.98,2512.02 ; R7.1@3104.99,2546.11 ccw(c3149.52,2543.56) 3117.98,2512.02 ; R7.1@3104.99,2546.11 ccw(c3149.52,2543.56) 3117.98,2512.02 ; 3123.39,2517.06 cw(c3152.32,2517.06) R7.1@3131.86,2537.51 ; 3123.39,2517.06 cw(c3152.32,2517.06) R7.1@3131.86,2537.51 ; 3123.39,2517.06 cw(c3152.32,2517.06) R7.1@3131.86,2537.51 ; R7.1@3134.94,2544.39 ccw(c3239.04,2538.42) 3165.31,2464.69 ; R7.1@3134.94,2544.39 ccw(c3239.04,2538.42) 3165.31,2464.69 ; R7.1@3134.94,2544.39 ccw(c3239.04,2538.42) 3165.31,2464.69
NetC10_1: C10.1 R7.2 TUSB3210.60 Y1.2 | length 1198.7
  Top Layer w10: Y1.2@2985,2445 3047.83,2507.83 TUSB3210.60@3047.83,2666.57 ; Y1.2@2985,2459.69 ccw(c2985,2495.14) 3010.07,2470.07 ; Y1.2@2985,2459.69 ccw(c2985,2495.14) 3010.07,2470.07 ; Y1.2@2985,2459.69 ccw(c2985,2495.14) 3010.07,2470.07 ; Y1.2@2999.69,2445 cw(c3035.14,2445) 3010.07,2470.07 ; Y1.2@2999.69,2445 cw(c3035.14,2445) 3010.07,2470.07 ; Y1.2@2999.69,2445 cw(c3035.14,2445) 3010.07,2470.07
  Bottom Layer w30: C10.1@2966.61,2345 2966.61,2426.61 Y1.2@2985,2445 3046.61,2506.61 R7.2@3046.61,2545 ; 2966.61,2389.3 cw(c3040.7,2389.3) Y1.2@2988.31,2441.69 ; 2966.61,2389.3 cw(c3040.7,2389.3) Y1.2@2988.31,2441.69 ; 2966.61,2389.3 cw(c3040.7,2389.3) Y1.2@2988.31,2441.69 ; 3004.69,2464.69 ccw(c2930.96,2538.42) R7.2@3035.06,2544.39 ; 3004.69,2464.69 ccw(c2930.96,2538.42) R7.2@3035.06,2544.39 ; 3004.69,2464.69 ccw(c2930.96,2538.42) R7.2@3035.06,2544.39 ; 3052.02,2512.02 ccw(c3020.48,2543.56) R7.2@3065.01,2546.11 ; 3052.02,2512.02 ccw(c3020.48,2543.56) R7.2@3065.01,2546.11 ; 3052.02,2512.02 ccw(c3020.48,2543.56) R7.2@3065.01,2546.11
NetC35_1: C35.1 MAX3232.1 | length 468.4
  Top Layer w20: MAX3232.1@3790,1790 3920,1790 4018.39,1691.61 C35.1@4090,1691.61 C35.1@4083.39,1685 ; 4052.36,1691.61 cw(c4052.36,1653.98) 4078.98,1680.59 ccw(c4052.36,1653.98) 4052.36,1691.61 ; 4052.36,1691.61 ccw(c4052.36,1729.25) 4078.98,1702.64 cw(c4052.36,1729.25) 4052.36,1691.61
NetC35_2: C35.2 MAX3232.3 | length 468.6
  Top Layer w20: MAX3232.3@3790,1890 3925,1890 4046.61,1768.39 C35.2@4090,1768.39 ; 4052.36,1768.39 cw(c4052.36,1730.75) 4078.98,1757.36 ccw(c4052.36,1730.75) 4052.36,1768.39 ; 4052.36,1768.39 ccw(c4052.36,1806.02) 4078.98,1779.41 cw(c4052.36,1806.02) 4052.36,1768.39
NetC37_2: C37.2 MAX3232.2 | length 506.8
  Top Layer w20: C37.2@3648.39,1690 3648.39,1805 3683.39,1840 MAX3232.2@3790,1840 ; 3648.39,1727.64 cw(c3610.75,1727.64) 3637.36,1701.02 ccw(c3610.75,1727.64) 3648.39,1727.64 ; 3648.39,1727.64 ccw(c3686.02,1727.64) 3659.41,1701.02 cw(c3686.02,1727.64) 3648.39,1727.64 ; MAX3232.2@3700,1840 ccw(c3700,1799.89) 3671.64,1828.25 cw(c3700,1799.89) MAX3232.2@3700,1840 ; MAX3232.2@3700,1840 ccw(c3695.85,1810.93) 3675.08,1831.69 cw(c3695.85,1810.93) MAX3232.2@3700,1840
NetC38_1: C38.1 MAX3232.4 | length 438.3
  Top Layer w20: MAX3232.4@3790,1940 3955,1940 4003.39,1891.61 C38.1@4090,1891.61 ; 4052.36,1891.61 cw(c4052.36,1853.98) 4078.98,1880.59 ccw(c4052.36,1853.98) 4052.36,1891.61 ; 4052.36,1891.61 ccw(c4052.36,1929.25) 4078.98,1902.64 cw(c4052.36,1929.25) 4052.36,1891.61
NetC38_2: C38.2 MAX3232.5 | length 427.2
  Top Layer w20: MAX3232.5@3790,1990 3985,1990 4006.61,1968.39 C38.2@4090,1968.39 ; 4052.36,1968.39 cw(c4052.36,1930.75) 4078.98,1957.36 ccw(c4052.36,1930.75) 4052.36,1968.39 ; 4052.36,1968.39 ccw(c4052.36,2006.02) 4078.98,1979.41 cw(c4052.36,2006.02) 4052.36,1968.39
NetC39_2: C39.2 MAX3232.6 | length 346.4
  Top Layer w20: MAX3232.6@3790,2040 3955,2040 3995,2080 C39.2@4001.61,2080 ; 3964.4,2049.4 cw(c4000.63,2013.18) 4000.63,2064.41 ccw(c4000.63,2013.18) 3964.4,2049.4 ; C39.2@3978,2063 ccw(c3960.99,2080) 3985.04,2080 cw(c3960.99,2080) C39.2@3978,2063
NetD0_2: D0.2 R1.2 | length 305.9
  Bottom Layer w30: D0.2@1955,3690 2031.61,3690 R1.2@2041.61,3700 ; 1993.63,3690 cw(c1993.63,3728.63) 1966.31,3701.31 ccw(c1993.63,3728.63) 1993.63,3690 ; 1993.63,3690 ccw(c1993.63,3651.37) 1966.31,3678.69 cw(c1993.63,3651.37) 1993.63,3690 ; 1990.92,3690 ccw(c1990.92,3749.71) 2033.14,3707.49 cw(c1990.92,3749.71) 1990.92,3690
NetD1_2: D1.2 R3.2 | length 305.9
  Bottom Layer w30: D1.2@1955,3470 2031.61,3470 R3.2@2041.61,3480 ; 1993.63,3470 cw(c1993.63,3508.63) 1966.31,3481.31 ccw(c1993.63,3508.63) 1993.63,3470 ; 1993.63,3470 ccw(c1993.63,3431.37) 1966.31,3458.69 cw(c1993.63,3431.37) 1993.63,3470 ; 1990.92,3470 ccw(c1990.92,3529.71) 2033.14,3487.49 cw(c1990.92,3529.71) 1990.92,3470
NetD2_2: D2.2 R4.2 | length 305.9
  Bottom Layer w30: D2.2@1955,3250 2031.61,3250 R4.2@2041.61,3240 ; 1993.63,3250 cw(c1993.63,3288.63) 1966.31,3261.31 ccw(c1993.63,3288.63) 1993.63,3250 ; 1993.63,3250 ccw(c1993.63,3211.37) 1966.31,3238.69 cw(c1993.63,3211.37) 1993.63,3250 ; 1990.92,3250 cw(c1990.92,3190.29) 2033.14,3232.51 ccw(c1990.92,3190.29) 1990.92,3250
NetD3_2: D3.2 R5.2 | length 305.9
  Bottom Layer w30: D3.2@1955,3030 2031.61,3030 R5.2@2041.61,3040 ; 1993.63,3030 cw(c1993.63,3068.63) 1966.31,3041.31 ccw(c1993.63,3068.63) 1993.63,3030 ; 1993.63,3030 ccw(c1993.63,2991.37) 1966.31,3018.69 cw(c1993.63,2991.37) 1993.63,3030 ; 1990.92,3030 ccw(c1990.92,3089.71) 2033.14,3047.49 cw(c1990.92,3089.71) 1990.92,3030
NetD4_2: D4.2 R6.2 | length 305.9
  Bottom Layer w30: D4.2@1955,2810 2031.61,2810 R6.2@2041.61,2800 ; 1993.63,2810 cw(c1993.63,2848.63) 1966.31,2821.31 ccw(c1993.63,2848.63) 1993.63,2810 ; 1993.63,2810 ccw(c1993.63,2771.37) 1966.31,2798.69 cw(c1993.63,2771.37) 1993.63,2810 ; 1990.92,2810 cw(c1990.92,2750.29) 2033.14,2792.51 ccw(c1990.92,2750.29) 1990.92,2810
NetD5_2: D5.2 R20.2 | length 305.9
  Bottom Layer w30: D5.2@1955,2590 2031.61,2590 R20.2@2041.61,2580 ; 1993.63,2590 cw(c1993.63,2628.63) 1966.31,2601.31 ccw(c1993.63,2628.63) 1993.63,2590 ; 1993.63,2590 ccw(c1993.63,2551.37) 1966.31,2578.69 cw(c1993.63,2551.37) 1993.63,2590 ; 1990.92,2590 cw(c1990.92,2530.29) 2033.14,2572.51 ccw(c1990.92,2530.29) 1990.92,2590
NetD6_2: D6.2 R21.2 | length 305.9
  Bottom Layer w30: D6.2@1955,2370 2031.61,2370 R21.2@2041.61,2360 ; 1993.63,2370 cw(c1993.63,2408.63) 1966.31,2381.31 ccw(c1993.63,2408.63) 1993.63,2370 ; 1993.63,2370 ccw(c1993.63,2331.37) 1966.31,2358.69 cw(c1993.63,2331.37) 1993.63,2370 ; 1990.92,2370 cw(c1990.92,2310.29) 2033.14,2352.51 ccw(c1990.92,2310.29) 1990.92,2370
NetD7_2: D7.2 R22.2 | length 305.9
  Bottom Layer w30: D7.2@1955,2150 2031.61,2150 R22.2@2041.61,2140 ; 1993.63,2150 cw(c1993.63,2188.63) 1966.31,2161.31 ccw(c1993.63,2188.63) 1993.63,2150 ; 1993.63,2150 ccw(c1993.63,2111.37) 1966.31,2138.69 cw(c1993.63,2111.37) 1993.63,2150 ; 1990.92,2150 cw(c1990.92,2090.29) 2033.14,2132.51 ccw(c1990.92,2090.29) 1990.92,2150
NetJ1_2: J1.2 R8.1 | length 348.4
  Bottom Layer w30: R8.1@3035,3488.39 3035,3550 3053.5,3568.5 J1.2@3053.5,3630 ; J1.2@3041.13,3617.63 cw(c3011.25,3587.75) 3053.5,3587.75 ; J1.2@3041.13,3617.63 cw(c3011.25,3587.75) 3053.5,3587.75 ; J1.2@3041.13,3617.63 cw(c3011.25,3587.75) 3053.5,3587.75 ; 3053.5,3587.75 cw(c3095.75,3587.75) J1.2@3065.87,3617.63 ; 3053.5,3587.75 cw(c3095.75,3587.75) J1.2@3065.87,3617.63 ; 3053.5,3587.75 cw(c3095.75,3587.75) J1.2@3065.87,3617.63
NetJ1_3: J1.3 R9.1 R12.2 | length 470.2
  Bottom Layer w30: J1.3@3132,3630 3132,3558 3155,3535 R9.1@3155,3488.39 R12.2@3275,3488.39 ; J1.3@3119.63,3617.63 cw(c3089.75,3587.75) 3132,3587.75 ; J1.3@3119.63,3617.63 cw(c3089.75,3587.75) 3132,3587.75 ; J1.3@3119.63,3617.63 cw(c3089.75,3587.75) 3132,3587.75 ; 3132,3587.75 cw(c3174.25,3587.75) J1.3@3144.37,3617.63 ; 3132,3587.75 cw(c3174.25,3587.75) J1.3@3144.37,3617.63 ; 3132,3587.75 cw(c3174.25,3587.75) J1.3@3144.37,3617.63
NetJP_COM1_2: JP_COM1.2 MAX3232.7 | length 1088.8
  Top Layer w20: MAX3232.7@3790,2090 3660,2090 3660,2175 3695,2210 4231.02,2210 JP_COM1.2@4310.08,2289.06 ; 4270.36,2249.33 cw(c4310.08,2209.61) 4310.08,2265.79 ccw(c4310.08,2209.61) 4270.36,2249.33 ; 4270.36,2249.33 ccw(c4230.64,2289.06) 4286.81,2289.06 cw(c4230.64,2289.06) 4270.36,2249.33
NetJP_COM1_3: JP_COM1.3 MAX3232.8 | length 713.1
  Top Layer w20: MAX3232.8@3790,2140 4270.08,2140 JP_COM1.3@4310.08,2180 ; 4270.36,2140.28 cw(c4310.08,2100.56) 4310.08,2156.73 ccw(c4310.08,2100.56) 4270.36,2140.28 ; 4270.36,2140.28 ccw(c4230.64,2180) 4286.81,2180 cw(c4230.64,2180) 4270.36,2140.28
NetPOW_1: POW.1 R2.2 | length 305
  Bottom Layer w30: R2.2@4470,3453.39 4491.61,3475 POW.1@4630,3475 ; R2.2@4477.49,3446.88 cw(c4545.37,3379) 4545.37,3475 ; POW.1@4618.69,3463.69 ccw(c4591.37,3436.37) 4591.37,3475 ccw(c4591.37,3513.63) POW.1@4618.69,3486.31
NetQ1_1: Q1.1 R12.1 | length 342.6
  Bottom Layer w20: R12.1@3275,3411.61 3311.61,3411.61 ; R12.1@3286.24,3400.81 cw(c3311.61,3376.42) 3311.61,3411.61 ; R12.1@3286.24,3422.42 ccw(c3311.61,3446.81) 3311.61,3411.61 ; Q1.1@3473.47,3463.15 ccw(c3456.93,3446.62) 3456.93,3470 ccw(c3456.93,3493.38) Q1.1@3473.47,3476.85 ; Q1.1@3500,3470 3370,3470 3311.61,3411.61
NetQ1_2: Q1.2 R13.1 | length 809.9
  Bottom Layer w20: R13.1@2915,3395.04 cw(c2915,3355.02) 2943.3,3383.32 ; R13.1@2915,3411.61 3066.61,3260 3265,3260 3425,3420 Q1.2@3500,3420 ; R13.1@2930.59,3410.63 ccw(c2965.85,3410.63) 2940.92,3385.7 ; Q1.2@3473.47,3413.15 ccw(c3456.93,3396.62) 3456.93,3420 ccw(c3456.93,3443.38) Q1.2@3473.47,3426.85
NetQ1_3: Q1.3 TUSB3210.17 | length 746.2
  Top Layer w10: TUSB3210.17@3126.57,3158.7 3337.87,3370 Q1.3@3500,3370 ; TUSB3210.17@3126.57,3162.91 ccw(c3126.57,3173.08) 3133.77,3165.89 ; TUSB3210.17@3126.57,3172.91 ccw(c3126.57,3207.23) 3150.84,3182.96 ; TUSB3210.17@3126.57,3182.91 ccw(c3126.57,3241.37) 3167.91,3200.03 ; TUSB3210.17@3126.57,3192.91 ccw(c3126.57,3275.51) 3184.98,3217.1 ; TUSB3210.17@3126.57,3202.91 ccw(c3126.57,3309.65) 3202.05,3234.18 ; Q1.3@3469.93,3359.62 ccw(c3444.86,3334.55) 3444.86,3370 ccw(c3444.86,3405.45) Q1.3@3469.93,3380.38
NetR8_2: R8.2 TP1.1 TUSB3210.19 | length 538.1
  Top Layer w10: TUSB3210.19@3087.2,3158.7 3087.2,3292.2 3100,3305 TP1.1@3100,3360 ; TP1.1@3092.93,3352.93 cw(c3075.86,3335.86) 3100,3335.86 ; TP1.1@3092.93,3352.93 cw(c3075.86,3335.86) 3100,3335.86 ; TP1.1@3092.93,3352.93 cw(c3075.86,3335.86) 3100,3335.86 ; 3100,3335.86 cw(c3124.14,3335.86) TP1.1@3107.07,3352.93 ; 3100,3335.86 cw(c3124.14,3335.86) TP1.1@3107.07,3352.93 ; 3100,3335.86 cw(c3124.14,3335.86) TP1.1@3107.07,3352.93
  Bottom Layer w30: R8.2@3035,3411.61 3048.39,3411.61 TP1.1@3092.5,3367.5 ; R8.2@3035,3400.04 cw(c3035,3339.78) 3077.61,3382.39 ; R8.2@3035,3400.04 cw(c3035,3339.78) 3077.61,3382.39 ; R8.2@3035,3400.04 cw(c3035,3339.78) 3077.61,3382.39
NetR9_2: R9.2 TP2.1 TUSB3210.18 | length 396.6
  Top Layer w10: TUSB3210.18@3106.89,3158.7 3106.89,3271.89 3140,3305 TP2.1@3140,3300 ; 3114.39,3279.39 cw(c3140,3253.79) TP2.1@3140,3290 ; 3114.39,3279.39 cw(c3140,3253.79) TP2.1@3140,3290 ; 3114.39,3279.39 cw(c3140,3253.79) TP2.1@3140,3290 ; 3126.46,3291.46 ccw(c3117.93,3300) TP2.1@3130,3300 ; 3126.46,3291.46 ccw(c3117.93,3300) TP2.1@3130,3300 ; 3126.46,3291.46 ccw(c3117.93,3300) TP2.1@3130,3300
  Bottom Layer w30: TP2.1@3140,3300 3140,3355 3155,3370 R9.2@3155,3411.61
NetR11_1: R11.1 SW1.2 | length 252.7
  Bottom Layer w30: SW1.2@4400,3137 4481.39,3137 R11.1@4520,3098.39 ; SW1.2@4417.68,3119.32 cw(c4460.36,3076.64) 4460.36,3137 cw(c4460.36,3197.36) SW1.2@4417.68,3154.68 ; R11.1@4500.24,3118.15 ccw(c4520,3137.91) R11.1@4520,3109.96
NetR15_2: R15.2 SUSP.1 | length 325
  Bottom Layer w30: SUSP.1@4170,3475 4328.39,3475 R15.2@4350,3453.39 ; SUSP.1@4181.31,3463.69 cw(c4208.63,3436.37) 4208.63,3475 cw(c4208.63,3513.63) SUSP.1@4181.31,3486.31 ; 4274.63,3475 cw(c4274.63,3379) R15.2@4342.51,3446.88
NetR16_2: R16.2 TUSB3210.8 | length 296
  Top Layer w10: TUSB3210.8@3225,2902.8 3387.2,2902.8 v1(3455,2835) ; v1@3445,2835 ccw(c3420.86,2835) 3437.93,2852.07 ccw(c3455,2869.14) v1@3455,2845
NetR17_2: R17.2 TUSB3210.9 | length 288.5
  Top Layer w10: TUSB3210.9@3225,2922.48 3422.48,2922.48 v1(3460,2960) ; v1@3450,2960 cw(c3425.86,2960) 3442.93,2942.93 cw(c3460,2925.86) v1@3460,2950
P0_0: P0.0---->P3.0.1 R1.1 TUSB3210.43 | length 3186.5
  Top Layer w10: P0.0---->P3.0.1@2220,2040 2175,2085 2175,2470 2568.43,2863.43 TUSB3210.43@2732.87,2863.43 ; 2178.13,2081.87 cw(c2136.26,2040) P0.0---->P3.0.1@2195.47,2040 ; 2178.13,2081.87 ccw(c2220,2123.74) P0.0---->P3.0.1@2220,2064.53 ; 2178.13,2081.87 cw(c2136.26,2040) P0.0---->P3.0.1@2195.47,2040 ; 2178.13,2081.87 ccw(c2220,2123.74) P0.0---->P3.0.1@2220,2064.53 ; 2178.13,2081.87 ccw(c2220,2123.74) P0.0---->P3.0.1@2220,2064.53 ; 2178.13,2081.87 cw(c2136.26,2040) P0.0---->P3.0.1@2195.47,2040 ; P0.0---->P3.0.1@2195.2,2064.8 cw(c2170.4,2040) P0.0---->P3.0.1@2205.47,2040 ; P0.0---->P3.0.1@2195.2,2064.8 ccw(c2220,2089.6) P0.0---->P3.0.1@2220,2054.53 ; P0.0---->P3.0.1@2195.2,2064.8 cw(c2170.4,2040) P0.0---->P3.0.1@2205.47,2040 ; P0.0---->P3.0.1@2195.2,2064.8 ccw(c2220,2089.6) P0.0---->P3.0.1@2220,2054.53 ; P0.0---->P3.0.1@2195.2,2064.8 ccw(c2220,2089.6) P0.0---->P3.0.1@2220,2054.53 ; P0.0---->P3.0.1@2195.2,2064.8 cw(c2170.4,2040) P0.0---->P3.0.1@2205.47,2040 ; 2487.93,2782.93 cw(c2505,2765.86) 2505,2790 ccw(c2505,2765.86) 2487.93,2782.93 ; 2487.93,2782.93 ccw(c2470.86,2800) 2495,2800 cw(c2470.86,2800) 2487.93,2782.93 ; 2522.07,2817.07 cw(c2505,2834.14) 2505,2810 ccw(c2505,2834.14) 2522.07,2817.07 ; 2522.07,2817.07 ccw(c2539.14,2800) 2515,2800 cw(c2539.14,2800) 2522.07,2817.07
  Bottom Layer w10: R1.1@2118.39,3700 2275,3543.39 2275,2885 2360,2800 v1(2505,2800) ; 2480.86,2800 cw(c2480.86,2775.86) 2497.93,2792.93 ccw(c2480.86,2775.86) 2480.86,2800 ; 2480.86,2800 ccw(c2480.86,2824.14) 2497.93,2807.07 cw(c2480.86,2824.14) 2480.86,2800 ; R1.1@2119.37,3679.41 cw(c2119.37,3632.08) 2152.84,3665.55 ccw(c2119.37,3632.08) R1.1@2119.37,3679.41 ; R1.1@2129.96,3700 ccw(c2157.91,3700) 2138.15,3680.24 cw(c2157.91,3700) R1.1@2129.96,3700 ; R1.1@2139.96,3700 ccw(c2192.05,3700) 2155.22,3663.17 cw(c2192.05,3700) R1.1@2139.96,3700
P0_1: P0.0---->P3.0.2 R3.1 TUSB3210.44 | length 2870
  Top Layer w10: P0.0---->P3.0.2@2220,2140 2220,2475 2520,2775 2520.36,2775 2535,2789.64 2535,2790 2588.74,2843.74 TUSB3210.44@2732.87,2843.74 ; P0.0---->P3.0.2@2202.66,2157.34 ccw(c2160.79,2199.21) 2220,2199.21 ; P0.0---->P3.0.2@2202.66,2157.34 ccw(c2160.79,2199.21) 2220,2199.21 ; P0.0---->P3.0.2@2202.66,2157.34 ccw(c2160.79,2199.21) 2220,2199.21 ; P0.0---->P3.0.2@2209.73,2150.27 ccw(c2184.93,2175.07) 2220,2175.07 ; P0.0---->P3.0.2@2209.73,2150.27 ccw(c2184.93,2175.07) 2220,2175.07 ; P0.0---->P3.0.2@2209.73,2150.27 ccw(c2184.93,2175.07) 2220,2175.07 ; 2220,2175.07 ccw(c2255.07,2175.07) P0.0---->P3.0.2@2230.27,2150.27 ; 2220,2175.07 ccw(c2255.07,2175.07) P0.0---->P3.0.2@2230.27,2150.27 ; 2220,2175.07 ccw(c2255.07,2175.07) P0.0---->P3.0.2@2230.27,2150.27 ; 2220,2199.21 ccw(c2279.21,2199.21) P0.0---->P3.0.2@2237.34,2157.34 ; 2220,2199.21 ccw(c2279.21,2199.21) P0.0---->P3.0.2@2237.34,2157.34 ; 2220,2199.21 ccw(c2279.21,2199.21) P0.0---->P3.0.2@2237.34,2157.34 ; 2482.93,2737.93 cw(c2500,2720.86) 2500,2745 ccw(c2500,2720.86) 2482.93,2737.93 ; 2482.93,2737.93 ccw(c2465.86,2755) 2490,2755 cw(c2465.86,2755) 2482.93,2737.93 ; 2517.07,2772.07 cw(c2500,2789.14) 2500,2765 ccw(c2500,2789.14) 2517.07,2772.07 ; 2517.07,2772.07 ccw(c2534.14,2755) 2510,2755 cw(c2534.14,2755) 2517.07,2772.07
  Bottom Layer w10: R3.1@2118.39,3480 2245,3353.39 2245,2815 2305,2755 v1(2500,2755) ; 2475.86,2755 cw(c2475.86,2730.86) 2492.93,2747.93 ccw(c2475.86,2730.86) 2475.86,2755 ; 2475.86,2755 ccw(c2475.86,2779.14) 2492.93,2762.07 cw(c2475.86,2779.14) 2475.86,2755 ; R3.1@2119.37,3459.41 cw(c2119.37,3412.08) 2152.84,3445.55 ccw(c2119.37,3412.08) R3.1@2119.37,3459.41 ; R3.1@2129.96,3480 ccw(c2157.91,3480) 2138.15,3460.24 cw(c2157.91,3480) R3.1@2129.96,3480 ; R3.1@2139.96,3480 ccw(c2192.05,3480) 2155.22,3443.17 cw(c2192.05,3480) R3.1@2139.96,3480
P0_2: P0.0---->P3.0.3 R4.1 TUSB3210.45 | length 2733
  Top Layer w10: P0.0---->P3.0.3@2320,2040 2270,2090 2270,2485 2609.05,2824.05 TUSB3210.45@2732.87,2824.05 ; 2278.13,2081.87 cw(c2236.26,2040) P0.0---->P3.0.3@2295.47,2040 ; 2278.13,2081.87 ccw(c2320,2123.74) P0.0---->P3.0.3@2320,2064.53 ; 2278.13,2081.87 cw(c2236.26,2040) P0.0---->P3.0.3@2295.47,2040 ; 2278.13,2081.87 ccw(c2320,2123.74) P0.0---->P3.0.3@2320,2064.53 ; 2278.13,2081.87 ccw(c2320,2123.74) P0.0---->P3.0.3@2320,2064.53 ; 2278.13,2081.87 cw(c2236.26,2040) P0.0---->P3.0.3@2295.47,2040 ; 2295.2,2064.8 cw(c2270.4,2040) P0.0---->P3.0.3@2305.47,2040 ; 2295.2,2064.8 ccw(c2320,2089.6) P0.0---->P3.0.3@2320,2054.53 ; 2295.2,2064.8 cw(c2270.4,2040) P0.0---->P3.0.3@2305.47,2040 ; 2295.2,2064.8 ccw(c2320,2089.6) P0.0---->P3.0.3@2320,2054.53 ; 2295.2,2064.8 ccw(c2320,2089.6) P0.0---->P3.0.3@2320,2054.53 ; 2295.2,2064.8 cw(c2270.4,2040) P0.0---->P3.0.3@2305.47,2040 ; 2477.93,2692.93 cw(c2495,2675.86) 2495,2700 ccw(c2495,2675.86) 2477.93,2692.93 ; 2477.93,2692.93 ccw(c2460.86,2710) 2485,2710 cw(c2460.86,2710) 2477.93,2692.93 ; 2512.07,2727.07 cw(c2495,2744.14) 2495,2720 ccw(c2495,2744.14) 2512.07,2727.07 ; 2512.07,2727.07 ccw(c2529.14,2710) 2505,2710 cw(c2529.14,2710) 2512.07,2727.07
  Bottom Layer w10: R4.1@2118.39,3240 2220,3138.39 2220,2785 2290,2715 2490,2715 v1(2495,2710) ; R4.1@2119.37,3219.41 cw(c2119.37,3172.08) 2152.84,3205.55 ccw(c2119.37,3172.08) R4.1@2119.37,3219.41 ; R4.1@2129.96,3240 ccw(c2157.91,3240) 2138.15,3220.24 cw(c2157.91,3240) R4.1@2129.96,3240 ; R4.1@2139.96,3240 ccw(c2192.05,3240) 2155.22,3203.17 cw(c2192.05,3240) R4.1@2139.96,3240 ; 2458.79,2715 cw(c2458.79,2673.79) 2487.93,2702.93 ccw(c2458.79,2673.79) 2458.79,2715
P0_3: P0.0---->P3.0.4 R5.1 TUSB3210.46 | length 2414
  Top Layer w10: P0.0---->P3.0.4@2320,2140 2320,2495 2629.37,2804.37 TUSB3210.46@2732.87,2804.37 ; P0.0---->P3.0.4@2302.66,2157.34 ccw(c2260.79,2199.21) 2320,2199.21 ; P0.0---->P3.0.4@2302.66,2157.34 ccw(c2260.79,2199.21) 2320,2199.21 ; P0.0---->P3.0.4@2302.66,2157.34 ccw(c2260.79,2199.21) 2320,2199.21 ; P0.0---->P3.0.4@2309.73,2150.27 ccw(c2284.93,2175.07) 2320,2175.07 ; P0.0---->P3.0.4@2309.73,2150.27 ccw(c2284.93,2175.07) 2320,2175.07 ; P0.0---->P3.0.4@2309.73,2150.27 ccw(c2284.93,2175.07) 2320,2175.07 ; 2320,2175.07 ccw(c2355.07,2175.07) P0.0---->P3.0.4@2330.27,2150.27 ; 2320,2175.07 ccw(c2355.07,2175.07) P0.0---->P3.0.4@2330.27,2150.27 ; 2320,2175.07 ccw(c2355.07,2175.07) P0.0---->P3.0.4@2330.27,2150.27 ; 2320,2199.21 ccw(c2379.21,2199.21) P0.0---->P3.0.4@2337.34,2157.34 ; 2320,2199.21 ccw(c2379.21,2199.21) P0.0---->P3.0.4@2337.34,2157.34 ; 2320,2199.21 ccw(c2379.21,2199.21) P0.0---->P3.0.4@2337.34,2157.34 ; 2472.93,2647.93 cw(c2490,2630.86) 2490,2655 ccw(c2490,2630.86) 2472.93,2647.93 ; 2472.93,2647.93 ccw(c2455.86,2665) 2480,2665 cw(c2455.86,2665) 2472.93,2647.93 ; 2507.07,2682.07 cw(c2490,2699.14) 2490,2675 ccw(c2490,2699.14) 2507.07,2682.07 ; 2507.07,2682.07 ccw(c2524.14,2665) 2500,2665 cw(c2524.14,2665) 2507.07,2682.07
  Bottom Layer w10: R5.1@2118.39,3040 2200,2958.39 2200,2755 2290,2665 v1(2490,2665) ; 2465.86,2665 cw(c2465.86,2640.86) 2482.93,2657.93 ccw(c2465.86,2640.86) 2465.86,2665 ; 2465.86,2665 ccw(c2465.86,2689.14) 2482.93,2672.07 cw(c2465.86,2689.14) 2465.86,2665 ; R5.1@2119.37,3019.41 cw(c2119.37,2972.08) 2152.84,3005.55 ccw(c2119.37,2972.08) R5.1@2119.37,3019.41 ; R5.1@2129.96,3040 ccw(c2157.91,3040) 2138.15,3020.24 cw(c2157.91,3040) R5.1@2129.96,3040 ; R5.1@2139.96,3040 ccw(c2192.05,3040) 2155.22,3003.17 cw(c2192.05,3040) R5.1@2139.96,3040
